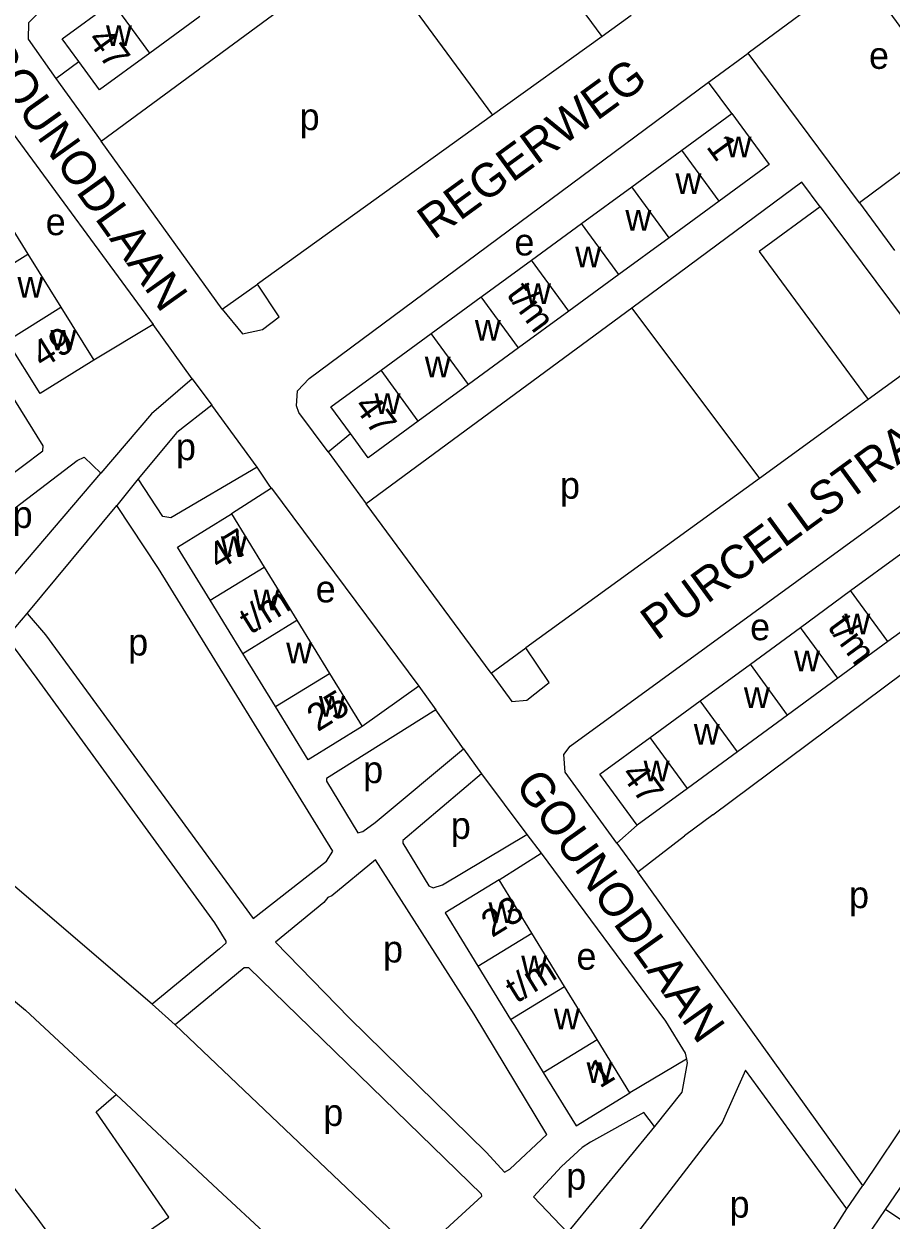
# Model space of a CAD drawing. Extents: x 159045 to 160918, y 380454 to 382516.
# Drawn here: x 159679 to 159808, y 382048.4 to 382226.3 of the extents above; entities that cross this region are included whole.
import ezdxf

# ---------------------------------------------------------------- set-up
doc = ezdxf.new("R2010")
doc.units = 0
for name, color, linetype in [('BLT_Basislijn', 7, 'Continuous'), ('BLT_Bebouwing', 7, 'Continuous'), ('BLT_Centroide', 7, 'Continuous'), ('BLT_Huisnummer_reeks', 7, 'Continuous'), ('BLT_Onderverdeling_panden', 7, 'Continuous'), ('BLT_Straatnaam', 7, 'Continuous')]:
    doc.layers.add(name, color=color, linetype=linetype)

msp = doc.modelspace()

# ---------------------------------------------------------------- linework, layer by layer
at = {"layer": 'BLT_Basislijn'}
for p, q in [((159690.49, 382208.86), (159730.09, 382238.05)), ((159730.09, 382238.05), (159748.74, 382212.73)), ((159769.36, 382227.57), (159765.01, 382224.43)), ((159765.01, 382224.43), (159748.74, 382212.73)), ((159803.32, 382199.69), (159786.75, 382221.97)), ((159683.77, 382218.18), (159687.17, 382220.74)), ((159683.77, 382218.18), (159690.49, 382208.86)), ((159784.35, 382213.01), (159780.87, 382217.67)), ((159676.15, 382211.66), (159698.24, 382181.63)), ((159748.74, 382212.73), (159713.75, 382187.6)), ((159708.49, 382183.92), (159690.49, 382208.86)), ((159794.75, 382202.79), (159769.47, 382184.05)), ((159797.47, 382199.13), (159794.75, 382202.79)), ((159797.47, 382199.13), (159814.93, 382175.65)), ((159708.49, 382183.92), (159713.75, 382187.6)), ((159769.47, 382184.05), (159729.94, 382154.95)), ((159769.47, 382184.05), (159788.45, 382158.73)), ((159698.24, 382181.63), (159689.38, 382176.29)), ((159704.01, 382173.53), (159698.24, 382181.63)), ((159809.67, 382174.13), (159804.59, 382170.44)), ((159704.01, 382173.53), (159706.96, 382169.61)), ((159804.59, 382170.44), (159788.45, 382158.73)), ((159713.68, 382160.38), (159706.96, 382169.61)), ((159724.26, 382162.67), (159727.57, 382165.43)), ((159724.26, 382162.67), (159729.94, 382154.95)), ((159676.66, 382143.33), (159690.44, 382159.51)), ((159696.01, 382158.66), (159692.84, 382154.71)), ((159788.45, 382158.73), (159753.68, 382133.51)), ((159715.84, 382157.27), (159709.87, 382153.46)), ((159715.84, 382157.27), (159737.75, 382127.82)), ((159679.48, 382138.63), (159692.84, 382154.71)), ((159748.52, 382129.74), (159729.94, 382154.95)), ((159676.12, 382134.68), (159679.48, 382138.63)), ((159748.52, 382129.74), (159753.68, 382133.51)), ((159781.48, 382108.7), (159809.76, 382129.75)), ((159737.75, 382127.82), (159729.33, 382121.81)), ((159737.75, 382127.82), (159740.31, 382124.32)), ((159744.41, 382118.52), (159740.31, 382124.32)), ((159744.41, 382118.52), (159747.08, 382114.8)), ((159747.08, 382114.8), (159753.83, 382105.79)), ((159781.48, 382108.7), (159777.26, 382105.55)), ((159767.24, 382104.49), (159770.25, 382107.15)), ((159753.83, 382105.79), (159755.95, 382103)), ((159767.24, 382104.49), (159770.35, 382100.23)), ((159770.35, 382100.23), (159777.26, 382105.55)), ((159749.69, 382099.02), (159755.95, 382103)), ((159698.06, 382080.56), (159675.89, 382099.55)), ((159803.84, 382053.57), (159770.35, 382100.23)), ((159674.47, 382083.57), (159679.24, 382079.65)), ((159692.72, 382067.09), (159679.24, 382079.65)), ((159698.06, 382080.56), (159701.5, 382077.49)), ((159737.54, 382043.2), (159701.5, 382077.49)), ((159777.58, 382072.34), (159769.15, 382067.36)), ((159707.87, 382052.97), (159692.72, 382067.09)), ((159772.82, 382062.33), (159759.86, 382046.61)), ((159715.32, 382046.03), (159707.87, 382052.97)), ((159801.46, 382050.11), (159803.84, 382053.57))]:
    msp.add_line(p, q, dxfattribs=at)
for points in [[(159741.23, 382271.89), (159681.76, 382228.56), (159679.69, 382226.46), (159679.63, 382224.04), (159683.77, 382218.18)], [(159765.01, 382224.43), (159749.07, 382246.09), (159758.43, 382252.99)], [(159828.17, 382185.23), (159832.35, 382187.88), (159833.75, 382189.79), (159833.84, 382191.98), (159833.49, 382192.83), (159805.09, 382231.83), (159801.28, 382232.72), (159786.75, 382221.97)], [(159780.87, 382217.67), (159781.73, 382218.31), (159786.75, 382221.97)], [(159724.26, 382162.67), (159719.92, 382168.54), (159719.54, 382169.5), (159719.7, 382171.76), (159721.45, 382173.57), (159780.87, 382217.67)], [(159664.54, 382191.37), (159656.8, 382203.85), (159640.74, 382193.7), (159640.7, 382193.06), (159641.57, 382191.37), (159669.14, 382153.63), (159669.66, 382153.69), (159681.81, 382162.85), (159681.86, 382163.55), (159664.54, 382191.37)], [(159797.47, 382199.13), (159788.4, 382192.45), (159804.59, 382170.44)], [(159708.49, 382183.92), (159711.5, 382180.25), (159714.52, 382180.85), (159717, 382182.78), (159713.75, 382187.6)], [(159704.01, 382173.53), (159697.99, 382168.35), (159690.44, 382159.51)], [(159706.96, 382169.61), (159701.73, 382165.55), (159696.01, 382158.66)], [(159676.66, 382143.33), (159671.9, 382149.39), (159672, 382150.04), (159686.94, 382161.4), (159687.94, 382161.89), (159690.44, 382159.51)], [(159767.24, 382104.49), (159759.53, 382115.02), (159759.34, 382117.67), (159760.25, 382118.93), (159820.98, 382163.06)], [(159713.68, 382160.38), (159700.86, 382152.85), (159699.67, 382153.06), (159696.01, 382158.66)], [(159715.84, 382157.27), (159715.61, 382157.57), (159713.68, 382160.38)], [(159679.48, 382138.63), (159682.23, 382135.46), (159713.12, 382093.27), (159724.03, 382101.82), (159724.95, 382103.28), (159699, 382145.33), (159692.84, 382154.71)], [(159676.12, 382134.68), (159677.56, 382133.52), (159680.9, 382128.99), (159707.34, 382092.65), (159709.05, 382089.93), (159709.05, 382089.6), (159708.11, 382088.75), (159698.06, 382080.56)], [(159748.52, 382129.74), (159751.57, 382125.55), (159753.83, 382125.77), (159757.14, 382128.38), (159753.68, 382133.51)], [(159740.31, 382124.32), (159724, 382114.1), (159724, 382113.68), (159728.67, 382106.02), (159729.4, 382106.21), (159731.27, 382107.56), (159744.41, 382118.52)], [(159747.08, 382114.8), (159735.4, 382104.89), (159735.4, 382104.48), (159739.26, 382098.12), (159739.9, 382097.85), (159741.29, 382098.27), (159753.83, 382105.79)], [(159755.95, 382103), (159774.44, 382078), (159777.38, 382073.24), (159777.58, 382072.34)], [(159745.98, 382079.04), (159731.31, 382102.01), (159724.82, 382096.64), (159724.22, 382096.42), (159723.63, 382095.65), (159716.43, 382089.77), (159727.38, 382078.5), (159747.83, 382058.5), (159750.49, 382055.58), (159751.28, 382055.99), (159756.82, 382061.15), (159745.98, 382079.04)], [(159833.36, 382097.58), (159803.84, 382053.57)], [(159737.54, 382043.2), (159747.15, 382052.01), (159747.1, 382052.29), (159712.48, 382085.95), (159711.75, 382085.95), (159701.5, 382077.49)], [(159786.34, 382070.72), (159782.9, 382062.95), (159766, 382040.96)], [(159777.58, 382072.34), (159777.69, 382071.81), (159776.9, 382067.47), (159772.82, 382062.33)], [(159801.46, 382050.11), (159786.34, 382070.72)], [(159687, 382039.57), (159700.56, 382048.86), (159689.76, 382064.51), (159692.72, 382067.09)], [(159772.82, 382062.33), (159771.22, 382064.41), (159763.32, 382060.02), (159762.07, 382059.24), (159759, 382056.42), (159754.83, 382051.91), (159759.86, 382046.61)], [(159766, 382040.96), (159784.18, 382025.13), (159785.11, 382025.32), (159795.15, 382040.18), (159801.46, 382050.11)]]:
    msp.add_lwpolyline(points, dxfattribs=at)
at = {"layer": 'BLT_Bebouwing'}
for p, q in [((159705.17, 382227.43), (159697.71, 382221.98)), ((159776.9, 382207.56), (159784.35, 382213.01)), ((159784.35, 382213.01), (159789.9, 382205.42)), ((159769.43, 382202.11), (159776.9, 382207.56)), ((159789.9, 382205.42), (159782.44, 382199.97)), ((159761.97, 382196.65), (159769.43, 382202.11)), ((159674.66, 382199.95), (159679.57, 382192.06)), ((159782.44, 382199.97), (159774.98, 382194.52)), ((159803.32, 382199.69), (159808.55, 382192.6)), ((159754.51, 382191.2), (159761.97, 382196.65)), ((159774.98, 382194.52), (159767.52, 382189.06)), ((159679.57, 382192.06), (159684.47, 382184.17)), ((159767.52, 382189.06), (159760.06, 382183.61)), ((159739.59, 382180.29), (159747.05, 382185.74)), ((159684.47, 382184.17), (159689.38, 382176.29)), ((159760.06, 382183.61), (159752.6, 382178.16)), ((159732.13, 382174.84), (159739.59, 382180.29)), ((159752.6, 382178.16), (159745.14, 382172.7)), ((159745.14, 382172.7), (159737.68, 382167.25)), ((159709.87, 382153.46), (159714.74, 382145.54)), ((159802, 382142.04), (159809.46, 382147.5)), ((159714.74, 382145.54), (159719.6, 382137.63)), ((159794.54, 382136.58), (159802, 382142.04)), ((159711.58, 382132.7), (159706.71, 382140.61)), ((159815.01, 382139.92), (159807.55, 382134.46)), ((159719.6, 382137.63), (159724.46, 382129.72)), ((159787.08, 382131.12), (159794.54, 382136.58)), ((159807.55, 382134.46), (159800.09, 382129)), ((159716.45, 382124.79), (159711.58, 382132.7)), ((159779.62, 382125.66), (159787.08, 382131.12)), ((159724.46, 382129.72), (159729.33, 382121.81)), ((159800.09, 382129), (159792.63, 382123.54)), ((159772.16, 382120.2), (159779.62, 382125.66)), ((159792.63, 382123.54), (159785.17, 382118.08)), ((159785.17, 382118.08), (159777.71, 382112.61)), ((159777.71, 382112.61), (159770.25, 382107.15)), ((159754.55, 382091.11), (159749.69, 382099.02)), ((159759.42, 382083.19), (159754.55, 382091.11)), ((159746.55, 382086.19), (159751.42, 382078.27)), ((159764.28, 382075.27), (159759.42, 382083.19)), ((159769.15, 382067.36), (159764.28, 382075.27)), ((159807.2, 382050.03), (159812.39, 382057.67)), ((159802.01, 382042.39), (159807.2, 382050.03))]:
    msp.add_line(p, q, dxfattribs=at)
for points in [[(159687.17, 382220.74), (159684.7, 382224.12), (159692.16, 382229.57)], [(159697.71, 382221.98), (159690.25, 382216.53), (159687.17, 382220.74)], [(159817.66, 382199.37), (159812.4, 382206.44), (159803.32, 382199.69)], [(159747.05, 382185.74), (159747.17, 382185.83), (159754.51, 382191.2)], [(159689.38, 382176.29), (159681.4, 382171.33), (159676.5, 382179.21)], [(159727.57, 382165.43), (159724.67, 382169.38), (159732.13, 382174.84)], [(159737.68, 382167.25), (159730.22, 382161.8), (159727.57, 382165.43)], [(159706.71, 382140.61), (159701.85, 382148.52), (159709.87, 382153.46)], [(159729.33, 382121.81), (159721.31, 382116.87), (159716.45, 382124.79)], [(159770.25, 382107.15), (159764.7, 382114.74), (159772.16, 382120.2)], [(159749.69, 382099.02), (159741.69, 382094.11), (159746.55, 382086.19)], [(159687, 382039.57), (159682.16, 382047.15), (159680.98, 382048.75), (159677.54, 382053.23), (159672.53, 382059), (159668.41, 382063.11), (159663.48, 382067.6), (159662.71, 382066.7), (159657.36, 382071.07), (159653.09, 382074.25), (159651.16, 382075.53), (159644.31, 382079.73), (159644.04, 382079.25), (159642.23, 382080.24)], [(159751.42, 382078.27), (159751.97, 382077.38), (159756.28, 382070.36)], [(159756.28, 382070.36), (159761.15, 382062.44), (159769.15, 382067.36)]]:
    msp.add_lwpolyline(points, dxfattribs=at)
at = {"layer": 'BLT_Onderverdeling_panden'}
for p, q in [((159697.71, 382221.98), (159692.16, 382229.57)), ((159782.44, 382199.97), (159776.9, 382207.56)), ((159774.98, 382194.52), (159769.43, 382202.11)), ((159767.52, 382189.06), (159761.97, 382196.65)), ((159671.59, 382187.1), (159679.57, 382192.06)), ((159760.06, 382183.61), (159754.51, 382191.2)), ((159752.6, 382178.16), (159747.05, 382185.74)), ((159676.5, 382179.21), (159684.47, 382184.17)), ((159745.14, 382172.7), (159739.59, 382180.29)), ((159737.68, 382167.25), (159732.13, 382174.84)), ((159706.71, 382140.61), (159714.74, 382145.54)), ((159807.55, 382134.46), (159802, 382142.04)), ((159711.58, 382132.7), (159719.6, 382137.63)), ((159800.09, 382129), (159794.54, 382136.58)), ((159792.63, 382123.54), (159787.08, 382131.12)), ((159716.45, 382124.79), (159724.46, 382129.72)), ((159785.17, 382118.08), (159779.62, 382125.66)), ((159777.71, 382112.61), (159772.16, 382120.2)), ((159746.55, 382086.19), (159754.55, 382091.11)), ((159751.42, 382078.27), (159759.42, 382083.19)), ((159756.28, 382070.36), (159764.28, 382075.27)), ((159814.4, 382045.14), (159807.2, 382050.03))]:
    msp.add_line(p, q, dxfattribs=at)

# ---------------------------------------------------------------- texts
at = {"layer": 'BLT_Centroide'}
for s, p in [('w', (159691.2, 382223.05)), ('e', (159804.73, 382219.63)), ('p', (159720.02, 382210.52)), ('w', (159783.39, 382206.48)), ('w', (159775.94, 382201.03)), ('w', (159768.48, 382195.58)), ('e', (159682.24, 382194.9)), ('e', (159751.98, 382191.88)), ('w', (159761.02, 382190.12)), ('w', (159678.03, 382185.62)), ('w', (159753.56, 382184.67)), ('w', (159746.09, 382179.22)), ('w', (159682.94, 382177.75)), ('w', (159738.64, 382173.77)), ('w', (159731.17, 382168.31)), ('p', (159701.62, 382161.44)), ('p', (159758.76, 382155.71)), ('p', (159677.32, 382151.36)), ('w', (159708.29, 382147.03)), ('w', (159713.16, 382139.12)), ('e', (159722.41, 382140.29)), ('w', (159801.05, 382135.52)), ('e', (159787.05, 382134.66)), ('p', (159694.51, 382132.39)), ('w', (159718.02, 382131.22)), ('w', (159793.58, 382130.06)), ('w', (159786.12, 382124.59)), ('w', (159722.89, 382123.28)), ('w', (159778.66, 382119.14)), ('p', (159729.47, 382113.42)), ('w', (159771.2, 382113.67)), ('p', (159742.51, 382105.12)), ('p', (159801.77, 382094.82)), ('w', (159748.12, 382092.59)), ('p', (159732.43, 382086.74)), ('e', (159761.21, 382085.67)), ('w', (159752.99, 382084.69)), ('w', (159757.85, 382076.78)), ('w', (159762.71, 382068.84)), ('p', (159723.54, 382062.43)), ('p', (159759.69, 382052.95)), ('p', (159783.99, 382048.8))]:
    msp.add_text(s, height=4, dxfattribs=at).set_placement(p)
at = {"layer": 'BLT_Huisnummer_reeks'}
for s, rotation, p in [('47', 306.1778, (159688.31, 382223.95)), ('1', 306.1686, (159780.41, 382208.04)), ('t/m', 306.1676, (159750.69, 382186.09)), ('49', 31.8805, (159681.75, 382175.01)), ('47', 306.169, (159727.97, 382169.44)), ('47', 31.5868, (159707.99, 382144.98)), ('t/m', 31.8786, (159712.69, 382135.44)), ('t/m', 306.2004, (159798.44, 382136.65)), ('25', 31.59, (159722.71, 382120.98)), ('47', 306.2017, (159767.71, 382114.69)), ('23', 31.5699, (159748.64, 382090.37)), ('t/m', 31.8786, (159752.28, 382080.58)), ('1', 31.5771, (159764.67, 382067.95))]:
    msp.add_text(s, height=4, rotation=rotation, dxfattribs=at).set_placement(p)
at = {"layer": 'BLT_Straatnaam'}
for s, rotation, p in [('GOUNODLAAN', 305.4218, (159672.01, 382221.93)), ('REGERWEG', 36.08, (159739.94, 382194.1)), ('PURCELLSTRAAT', 36.1145, (159773.16, 382134.51)), ('GOUNODLAAN', 305.4218, (159751.94, 382113.13))]:
    msp.add_text(s, height=5, rotation=rotation, dxfattribs=at).set_placement(p)

doc.saveas('drawing.dxf')
